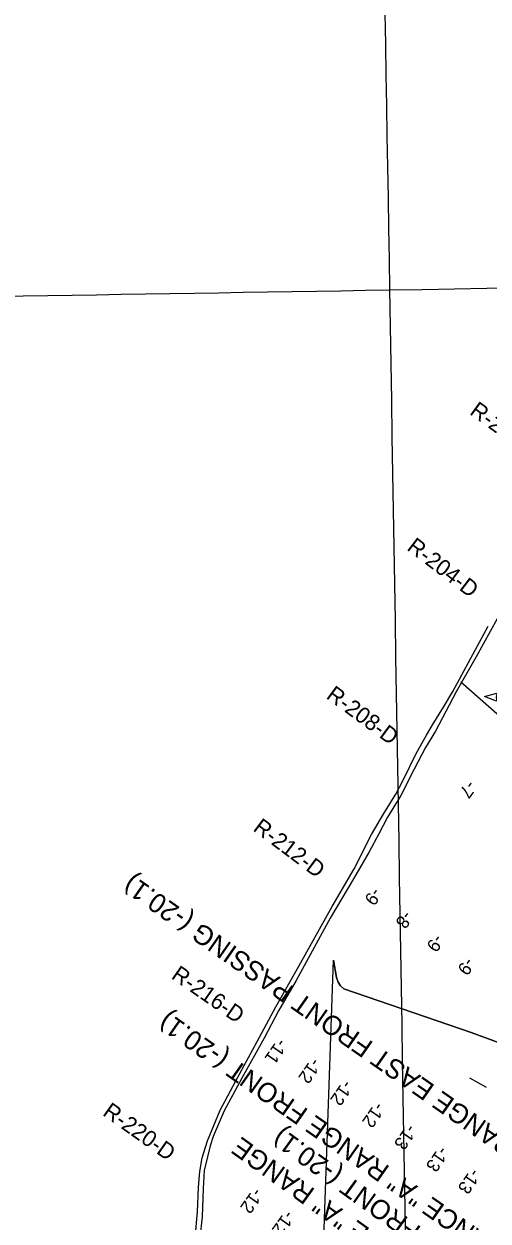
# Model space of a CAD drawing. Extents: x 3879599 to 3900814, y 146526 to 168888.
# Drawn here: x 3887805 to 3889001, y 154174 to 157260 of the extents above; entities that cross this region are included whole.
import ezdxf

# ---------------------------------------------------------------- set-up
doc = ezdxf.new("R2010")
doc.units = 0
for name, color, linetype in [('V-CHAN-NAID', 7, 'Continuous'), ('V-GRID-MAJR', 7, 'Continuous'), ('V-LEVE-TOET', 7, 'Continuous'), ('V-RIVR-JETY', 7, 'Continuous'), ('V-RIVR-RANG', 7, 'Continuous'), ('V-RIVR-RANG-IDEN', 7, 'Continuous'), ('V-TOPO-DPTH', 7, 'Continuous'), ('V-TOPO-MINR', 7, 'Continuous')]:
    doc.layers.add(name, color=color, linetype=linetype)

msp = doc.modelspace()

# ---------------------------------------------------------------- linework, layer by layer
at = {"layer": 'V-CHAN-NAID'}
msp.add_lwpolyline([(3889023.4, 155519.3), (3889023.2, 155514.5), (3888991.8, 155526), (3889024, 155535.1), (3889023.8, 155530.4), (3889023.5, 155529.6), (3889023.2, 155528.7), (3889022.9, 155527.6), (3889022.7, 155526.7), (3889022.6, 155525.6), (3889022.5, 155524.5), (3889022.6, 155523.5), (3889022.6, 155522.7), (3889022.8, 155521.7), (3889022.9, 155520.8), (3889023.2, 155519.9)], close=True, dxfattribs=at)
at = {"layer": 'V-GRID-MAJR'}
for points in [[(3888895.8, 147678.8), (3888848.8, 150514.5), (3888748.3, 156574.8), (3888664.2, 161644.6)], [(3884717.1, 156508.2), (3888748.3, 156574.8), (3894080.4, 156663.6), (3896663.2, 156706.9)]]:
    msp.add_spline(points, degree=3, dxfattribs=at)
at = {"layer": 'V-LEVE-TOET'}
msp.add_line((3888997.5, 154518.1), (3888954.3, 154542), dxfattribs=at)
msp.add_lwpolyline([(3889814.8, 154859.8), (3889673.1, 154970.8), (3889552.8, 155064), (3889451.2, 155140.7), (3889345.4, 155224.9), (3889250.1, 155300.5), (3889138.3, 155389.8), (3889023.6, 155481.6), (3888930.9, 155563.5)], dxfattribs=at)
at = {"layer": 'V-RIVR-JETY'}
for points in [[(3889024.5, 155726.9), (3888970.4, 155628.7), (3888919.3, 155538.3), (3888865.9, 155437.4), (3888839.9, 155394.9), (3888811.1, 155339.2), (3888776.4, 155270.9), (3888742.6, 155215.5), (3888720.2, 155172.7), (3888695, 155126.1), (3888654.8, 155056.7), (3888594.4, 154955), (3888558.4, 154888.4), (3888506.6, 154794.4), (3888461.6, 154715.6), (3888424.2, 154645.5), (3888367, 154542.1), (3888321.1, 154458.3), (3888292.7, 154392.1), (3888285, 154367.7), (3888278.3, 154339.4), (3888270.1, 154304.1)], [(3888242.8, 154092.1), (3888252.3, 154198.1), (3888255.3, 154261.5), (3888258.3, 154301.5), (3888264.5, 154336.8), (3888278.2, 154380.5), (3888310.6, 154460.2), (3888350.1, 154533.5), (3888406.6, 154636.9), (3888454.2, 154726.3), (3888513.8, 154831.4), (3888599.6, 154984.6), (3888655.9, 155081.8), (3888701.1, 155170.7), (3888732.8, 155225.1), (3888763.8, 155274.6), (3888782.2, 155310.7), (3888816.5, 155379.3), (3888842.3, 155427), (3888857.3, 155451.9), (3888886.7, 155499.2), (3888910.2, 155539.2), (3888957.2, 155625.1), (3889001.4, 155707.5)], [(3888270.1, 154304.1), (3888267.2, 154257.8), (3888264.2, 154185.3), (3888258.3, 154129.9), (3888239.4, 154000.5), (3888229.7, 153915.8), (3888218.4, 153870.1), (3888206, 153834.1), (3888195.1, 153814.4), (3888181.7, 153796.2), (3888135.4, 153745.5), (3888087.8, 153710), (3888086.3, 153717.3)]]:
    msp.add_lwpolyline(points, dxfattribs=at)
at = {"layer": 'V-TOPO-DPTH'}
msp.add_line((3888556.8, 153520.2), (3888603.3, 154846.2), dxfattribs=at)
msp.add_lwpolyline([(3888603.3, 154846.2), (3888610.8, 154801.6), (3888614.9, 154790), (3888621, 154780.1), (3888630, 154772.7), (3888957.4, 154660.1), (3889100.6, 154607.9)], dxfattribs=at)
at = {"layer": 'V-TOPO-MINR'}
msp.add_lwpolyline([(3889100.6, 154607.9), (3888957.4, 154660.1), (3888630, 154772.7), (3888621, 154780.1), (3888614.9, 154790), (3888610.8, 154801.6), (3888603.3, 154846.2)], dxfattribs=at)

# ---------------------------------------------------------------- texts
at = {"layer": 'V-CHAN-NAID'}
for s, rotation, p in [('ENTRANCE "A" RANGE EAST FRONT PASSING (-20.1)', 145.0553, (3889484.3, 154091)), ('ENTRANCE "A" RANGE FRONT (-20.1)', 144.9757, (3889157.6, 154027.6)), ('WEST FRONT (-20.1)', 144.314, (3889003.7, 154033.4)), ('ENTRANCE "A" RANGE', 144.314, (3888961.8, 153964.5))]:
    msp.add_text(s, height=50, rotation=rotation, dxfattribs=at).set_placement(p)
at = {"layer": 'V-RIVR-RANG'}
for s, rotation, p in [('-7', 233.5583, (3888948.6, 155312.5)), ('-9', 232.9683, (3888704.8, 155036.2)), ('-8', 232.9683, (3888785, 154976.5)), ('-9', 232.9683, (3888864.8, 154916.1)), ('-9', 232.9683, (3888944.7, 154856.1)), ('-11', 235.1083, (3888460.9, 154647.3)), ('-12', 235.1083, (3888547.8, 154597.1)), ('-12', 235.1083, (3888630, 154540.1)), ('-12', 235.1083, (3888712.1, 154483.1)), ('-13', 235.1083, (3888794.4, 154426.3)), ('-13', 235.1083, (3888876.6, 154369.3)), ('-13', 235.1083, (3888958.8, 154312.3)), ('-12', 234.5083, (3888398.4, 154261.9)), ('-12', 234.5083, (3888480, 154204.1))]:
    msp.add_text(s, height=33.5, rotation=rotation, dxfattribs=at).set_placement(p)
at = {"layer": 'V-RIVR-RANG-IDEN'}
for s, rotation, p in [('R-200-D', 324.0718, (3888951.6, 156256)), ('R-204-D', 322.6147, (3888789.8, 155906.1)), ('R-208-D', 323.691, (3888581.8, 155523.5)), ('R-212-D', 323.1049, (3888393.3, 155182.2)), ('R-216-D', 325.2537, (3888182.5, 154801.2)), ('R-220-D', 324.6519, (3888005.7, 154448.5))]:
    msp.add_text(s, height=41.5, rotation=rotation, dxfattribs=at).set_placement(p)

doc.saveas('drawing.dxf')
